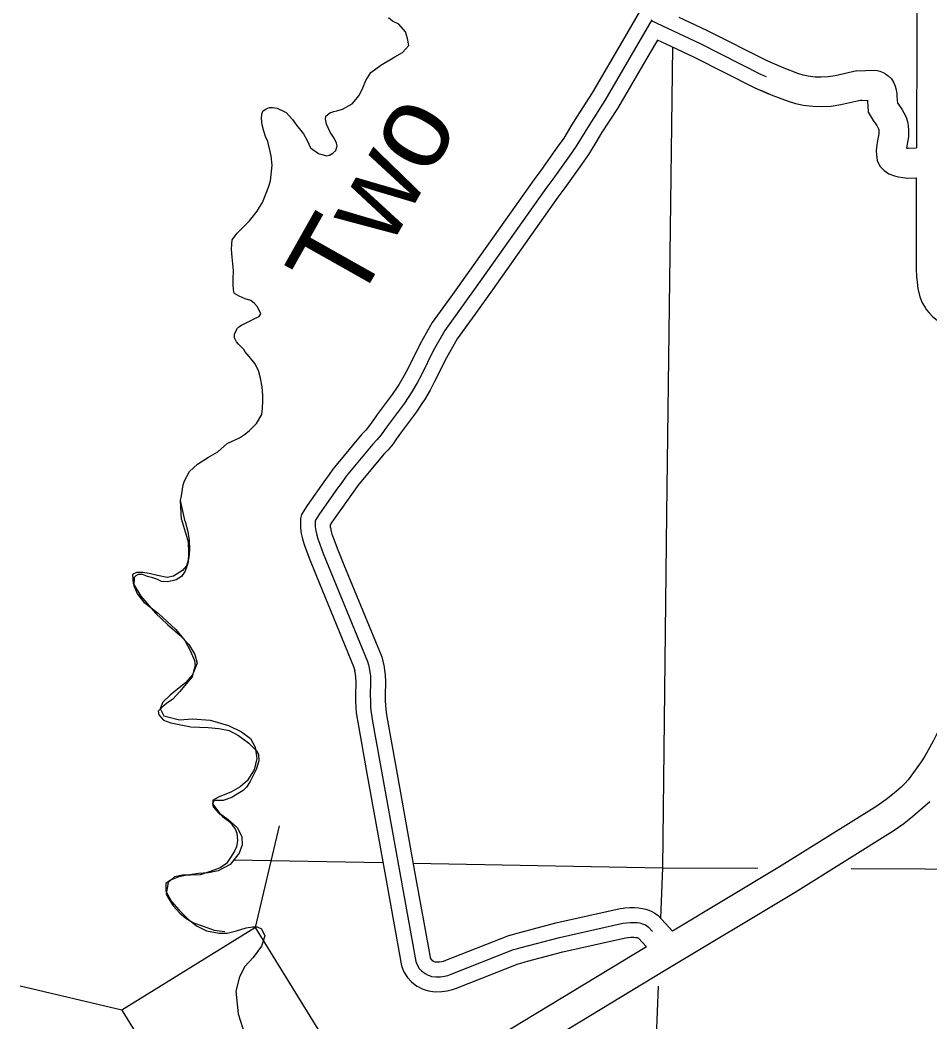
# Model space of a CAD drawing. Extents: x 1373094 to 1376427, y 1168361 to 1170494.
# Drawn here: x 1373276.1 to 1373352.6, y 1170074.3 to 1170158.6 of the extents above; entities that cross this region are included whole.
import ezdxf

# ---------------------------------------------------------------- set-up
doc = ezdxf.new("R2010")
doc.units = 0
doc.layers.add('R_Axis', color=7, linetype='Continuous')

msp = doc.modelspace()

# ---------------------------------------------------------------- linework, layer by layer
at = {"layer": 'R_Axis'}
for p, q in [((1373295.886, 1170082.215), (1373297.91, 1170090.779)), ((1373295.886, 1170082.215), (1373284.656, 1170075.278)), ((1373316.696, 1170048.524), (1373295.886, 1170082.215)), ((1373284.656, 1170075.278), (1373276.091, 1170077.302)), ((1373284.656, 1170075.278), (1373305.466, 1170041.587))]:
    msp.add_line(p, q, dxfattribs=at)
for points in [[(1373351.823, 1170177.904), (1373351.568, 1170164.434), (1373351.515, 1170157.726), (1373351.489, 1170147.798)], [(1373331.466, 1170164.647), (1373328.167, 1170159.211), (1373326.926, 1170157.083)], [(1373329.241, 1170158.572), (1373325.28, 1170151.78), (1373323.95, 1170149.722), (1373322.866, 1170147.935), (1373322.297, 1170147.141), (1373320.899, 1170145.182), (1373320.313, 1170144.388), (1373314.805, 1170136.587), (1373311.814, 1170132.432), (1373310.845, 1170130.73), (1373309.847, 1170128.71), (1373309.492, 1170128.037), (1373309.039, 1170127.278), (1373308.423, 1170126.334), (1373307.154, 1170124.661), (1373306.926, 1170124.323), (1373306.715, 1170124.019), (1373306.471, 1170123.681), (1373306.113, 1170123.242), (1373305.769, 1170122.885), (1373303.519, 1170120.178), (1373303.097, 1170119.587), (1373302.804, 1170119.182), (1373301.277, 1170117.021), (1373300.936, 1170116.481)], [(1373308.783, 1170156.41), (1373308.679, 1170157.011), (1373308.509, 1170157.577), (1373307.94, 1170158.208), (1373307.407, 1170158.472), (1373307.072, 1170158.737)], [(1373308.783, 1170156.41), (1373308.679, 1170157.011), (1373308.509, 1170157.577), (1373307.94, 1170158.208), (1373307.407, 1170158.472), (1373307.072, 1170158.737)], [(1373338.886, 1170153.774), (1373338.453, 1170153.956), (1373333.318, 1170156.548), (1373329.198, 1170158.501)], [(1373338.977, 1170155.091), (1373333.868, 1170157.671), (1373331.524, 1170158.782)], [(1373289.989, 1170116.379), (1373289.598, 1170118.148), (1373289.662, 1170118.549), (1373289.822, 1170119.452), (1373289.919, 1170119.786), (1373290.346, 1170120.589), (1373291.007, 1170121.194), (1373291.933, 1170121.8), (1373292.728, 1170122.239), (1373293.521, 1170122.944), (1373294.548, 1170123.417), (1373294.978, 1170123.687), (1373295.375, 1170123.99), (1373295.969, 1170124.627), (1373296.429, 1170125.364), (1373296.492, 1170125.865), (1373296.521, 1170126.566), (1373296.518, 1170126.967), (1373296.447, 1170127.701), (1373296.309, 1170128.434), (1373296.138, 1170129.068), (1373295.835, 1170129.667), (1373295.366, 1170130.265), (1373294.998, 1170130.663), (1373294.93, 1170130.83), (1373294.461, 1170131.294), (1373294.294, 1170131.493), (1373294.126, 1170131.826), (1373294.123, 1170132.16), (1373294.386, 1170132.629), (1373294.485, 1170132.763), (1373294.717, 1170132.898), (1373295.942, 1170133.506), (1373296.207, 1170133.607), (1373296.339, 1170133.842), (1373296.237, 1170134.108), (1373296.035, 1170134.474), (1373295.801, 1170134.706), (1373295.5, 1170134.972), (1373295.034, 1170135.102), (1373294.534, 1170135.333), (1373294.134, 1170135.565), (1373294.066, 1170135.664), (1373294.029, 1170136.232), (1373294.026, 1170136.766), (1373294.054, 1170137.5), (1373293.947, 1170138.601), (1373293.876, 1170139.268), (1373293.906, 1170139.702), (1373293.937, 1170140.069), (1373294.365, 1170140.639), (1373295.389, 1170141.68), (1373296.048, 1170142.485), (1373296.245, 1170142.82), (1373296.475, 1170143.222), (1373296.998, 1170144.493), (1373297.161, 1170145.028), (1373297.285, 1170146.364), (1373297.213, 1170147.131), (1373296.939, 1170148.331), (1373296.737, 1170148.764), (1373296.601, 1170149.197), (1373296.464, 1170149.73), (1373296.394, 1170150.264), (1373296.425, 1170150.631), (1373296.523, 1170150.899), (1373296.787, 1170151.101), (1373297.086, 1170151.202), (1373297.319, 1170151.204), (1373297.718, 1170151.139), (1373298.485, 1170150.777), (1373299.02, 1170150.179), (1373299.356, 1170149.714), (1373299.926, 1170148.983), (1373300.229, 1170148.417), (1373300.532, 1170147.818), (1373301.2, 1170147.321), (1373301.866, 1170147.125), (1373302.132, 1170147.193), (1373302.396, 1170147.361), (1373302.661, 1170147.597), (1373302.758, 1170147.964), (1373302.723, 1170148.198), (1373302.521, 1170148.631), (1373302.185, 1170149.129), (1373301.881, 1170149.795), (1373301.779, 1170150.228), (1373301.81, 1170150.462), (1373302.141, 1170150.764), (1373302.472, 1170150.867), (1373302.738, 1170150.935), (1373303.202, 1170151.071), (1373304.03, 1170151.51), (1373304.624, 1170152.214), (1373304.919, 1170152.85), (1373305.18, 1170153.486), (1373305.608, 1170154.156), (1373306.434, 1170154.761), (1373307.626, 1170155.469), (1373308.255, 1170155.84), (1373308.783, 1170156.41)], [(1373289.672, 1170116.536), (1373289.598, 1170118.148), (1373289.662, 1170118.549), (1373289.822, 1170119.452), (1373289.919, 1170119.786), (1373290.346, 1170120.589), (1373291.007, 1170121.194), (1373291.933, 1170121.8), (1373292.728, 1170122.239), (1373293.521, 1170122.944), (1373294.548, 1170123.417), (1373294.978, 1170123.687), (1373295.375, 1170123.99), (1373295.969, 1170124.627), (1373296.429, 1170125.364), (1373296.492, 1170125.865), (1373296.521, 1170126.566), (1373296.518, 1170126.967), (1373296.447, 1170127.701), (1373296.309, 1170128.434), (1373296.138, 1170129.068), (1373295.835, 1170129.667), (1373295.366, 1170130.265), (1373294.998, 1170130.663), (1373294.93, 1170130.83), (1373294.461, 1170131.294), (1373294.294, 1170131.493), (1373294.126, 1170131.826), (1373294.123, 1170132.16), (1373294.386, 1170132.629), (1373294.485, 1170132.763), (1373294.717, 1170132.898), (1373295.942, 1170133.506), (1373296.207, 1170133.607), (1373296.339, 1170133.842), (1373296.237, 1170134.108), (1373296.035, 1170134.474), (1373295.801, 1170134.706), (1373295.5, 1170134.972), (1373295.034, 1170135.102), (1373294.534, 1170135.333), (1373294.134, 1170135.565), (1373294.066, 1170135.664), (1373294.029, 1170136.232), (1373294.026, 1170136.766), (1373294.054, 1170137.5), (1373293.947, 1170138.601), (1373293.876, 1170139.268), (1373293.906, 1170139.702), (1373293.937, 1170140.069), (1373294.365, 1170140.639), (1373295.389, 1170141.68), (1373296.048, 1170142.485), (1373296.245, 1170142.82), (1373296.475, 1170143.222), (1373296.998, 1170144.493), (1373297.161, 1170145.028), (1373297.285, 1170146.364), (1373297.213, 1170147.131), (1373296.939, 1170148.331), (1373296.737, 1170148.764), (1373296.601, 1170149.197), (1373296.464, 1170149.73), (1373296.394, 1170150.264), (1373296.425, 1170150.631), (1373296.523, 1170150.899), (1373296.787, 1170151.101), (1373297.086, 1170151.202), (1373297.319, 1170151.204), (1373297.718, 1170151.139), (1373298.485, 1170150.777), (1373299.02, 1170150.179), (1373299.356, 1170149.714), (1373299.926, 1170148.983), (1373300.229, 1170148.417), (1373300.532, 1170147.818), (1373301.2, 1170147.321), (1373301.866, 1170147.125), (1373302.132, 1170147.193), (1373302.396, 1170147.361), (1373302.661, 1170147.597), (1373302.758, 1170147.964), (1373302.723, 1170148.198), (1373302.521, 1170148.631), (1373302.185, 1170149.129), (1373301.881, 1170149.795), (1373301.779, 1170150.228), (1373301.81, 1170150.462), (1373302.141, 1170150.764), (1373302.472, 1170150.867), (1373302.738, 1170150.935), (1373303.202, 1170151.071), (1373304.03, 1170151.51), (1373304.624, 1170152.214), (1373304.919, 1170152.85), (1373305.18, 1170153.486), (1373305.608, 1170154.156), (1373306.434, 1170154.761), (1373307.626, 1170155.469), (1373308.255, 1170155.84), (1373308.783, 1170156.41)], [(1373326.926, 1170157.083), (1373324.214, 1170152.434), (1373322.891, 1170150.385), (1373322.394, 1170149.567)], [(1373329.701, 1170156.879), (1373329.085, 1170155.823)], [(1373330.453, 1170156.522), (1373329.701, 1170156.879)], [(1373339.084, 1170152.335), (1373337.929, 1170152.82), (1373332.769, 1170155.425), (1373330.453, 1170156.522)], [(1373330.96, 1170156.282), (1373330.476, 1170117.025)], [(1373329.085, 1170155.823), (1373326.345, 1170151.125), (1373325.01, 1170149.058), (1373324.531, 1170148.27)], [(1373346.476, 1170154.276), (1373344.667, 1170153.877), (1373344.052, 1170153.785), (1373343.487, 1170153.75), (1373342.971, 1170153.767), (1373342.383, 1170153.844), (1373341.967, 1170153.934), (1373341.516, 1170154.064), (1373340.378, 1170154.504), (1373338.977, 1170155.091)], [(1373346.476, 1170154.276), (1373347.93, 1170154.338), (1373348.173, 1170154.303), (1373348.422, 1170154.255), (1373348.697, 1170154.137), (1373348.877, 1170154.037), (1373349.112, 1170153.876), (1373349.381, 1170153.607), (1373349.582, 1170153.276), (1373349.706, 1170152.987), (1373349.79, 1170152.692), (1373349.83, 1170152.362), (1373349.848, 1170152.139), (1373349.87, 1170151.848), (1373349.888, 1170151.568), (1373349.914, 1170151.528), (1373350.259, 1170151.07), (1373350.443, 1170150.745), (1373350.62, 1170150.376), (1373350.727, 1170150.029), (1373350.799, 1170149.681), (1373350.832, 1170149.265), (1373350.817, 1170148.745), (1373350.708, 1170148.104), (1373350.643, 1170147.786), (1373350.793, 1170147.774), (1373351.489, 1170147.798)], [(1373346.907, 1170151.811), (1373345.121, 1170151.417), (1373344.315, 1170151.297), (1373343.524, 1170151.247), (1373342.768, 1170151.273), (1373341.956, 1170151.378), (1373341.355, 1170151.509), (1373340.718, 1170151.693), (1373339.444, 1170152.184), (1373338.402, 1170152.621)], [(1373346.691, 1170151.782), (1373347.365, 1170151.811), (1373347.376, 1170151.671), (1373347.398, 1170151.332), (1373347.443, 1170150.8), (1373347.682, 1170150.376), (1373347.863, 1170150.096), (1373348.164, 1170149.696), (1373348.225, 1170149.589), (1373348.285, 1170149.462), (1373348.303, 1170149.404), (1373348.32, 1170149.326), (1373348.329, 1170149.202), (1373348.323, 1170148.992), (1373348.25, 1170148.562), (1373348.148, 1170148.061), (1373348.107, 1170147.597), (1373348.12, 1170147.214), (1373348.193, 1170146.736), (1373348.425, 1170146.26), (1373348.767, 1170145.896), (1373349.173, 1170145.614), (1373349.634, 1170145.443), (1373349.975, 1170145.356), (1373350.333, 1170145.302), (1373350.74, 1170145.271), (1373351.481, 1170145.296)], [(1373322.394, 1170149.567), (1373321.822, 1170148.624), (1373321.28, 1170147.868), (1373319.887, 1170145.916), (1373319.3, 1170145.119), (1373317.401, 1170142.43)], [(1373324.531, 1170148.27), (1373323.91, 1170147.245), (1373323.314, 1170146.414), (1373321.911, 1170144.448), (1373321.327, 1170143.656), (1373319.443, 1170140.988)], [(1373351.481, 1170145.296), (1373351.455, 1170137.596), (1373351.488, 1170136.994), (1373351.542, 1170136.51), (1373351.611, 1170135.971), (1373351.766, 1170135.282), (1373351.967, 1170134.769), (1373352.214, 1170134.388), (1373352.339, 1170134.194), (1373352.538, 1170133.952), (1373352.868, 1170133.586), (1373353.333, 1170133.225), (1373353.885, 1170132.91), (1373354.408, 1170132.719), (1373354.879, 1170132.61)], [(1373317.401, 1170142.43), (1373313.787, 1170137.312), (1373312.313, 1170135.264)], [(1373319.443, 1170140.988), (1373315.823, 1170135.861), (1373314.342, 1170133.803)], [(1373312.313, 1170135.264), (1373310.761, 1170133.108), (1373309.74, 1170131.317), (1373308.734, 1170129.279), (1373308.402, 1170128.649), (1373307.979, 1170127.941), (1373307.799, 1170127.665)], [(1373314.342, 1170133.803), (1373312.867, 1170131.755), (1373311.949, 1170130.143), (1373310.961, 1170128.142), (1373310.583, 1170127.425), (1373310.1, 1170126.616), (1373309.893, 1170126.299)], [(1373307.799, 1170127.665), (1373307.4, 1170127.054), (1373306.136, 1170125.388), (1373305.895, 1170125.029), (1373305.695, 1170124.742), (1373305.479, 1170124.443), (1373305.177, 1170124.072), (1373304.838, 1170123.72), (1373302.529, 1170120.942), (1373302.415, 1170120.783)], [(1373309.893, 1170126.299), (1373309.446, 1170125.613), (1373308.171, 1170123.933), (1373307.958, 1170123.617), (1373307.735, 1170123.297), (1373307.463, 1170122.92), (1373307.049, 1170122.411), (1373306.701, 1170122.051), (1373304.51, 1170119.414), (1373304.449, 1170119.329)], [(1373302.415, 1170120.783), (1373302.081, 1170120.317), (1373301.787, 1170119.909), (1373300.237, 1170117.715), (1373299.757, 1170116.954), (1373299.691, 1170116.628), (1373299.679, 1170116.512), (1373299.671, 1170116.416), (1373299.668, 1170116.298), (1373299.671, 1170116.069), (1373299.682, 1170115.842), (1373299.704, 1170115.602), (1373299.741, 1170115.365), (1373299.84, 1170114.922), (1373299.952, 1170114.528), (1373300.131, 1170114.039), (1373300.429, 1170113.223), (1373301.019, 1170111.787)], [(1373304.449, 1170119.329), (1373304.112, 1170118.858), (1373303.821, 1170118.455), (1373302.316, 1170116.326), (1373302.172, 1170116.097), (1373302.176, 1170116.016), (1373302.186, 1170115.915), (1373302.198, 1170115.833), (1373302.265, 1170115.535), (1373302.331, 1170115.3), (1373302.479, 1170114.898), (1373302.76, 1170114.128), (1373303.331, 1170112.737)], [(1373330.476, 1170117.025), (1373330.133, 1170087.243), (1373329.971, 1170083.005)], [(1373355.092, 1170117.343), (1373355.103, 1170110.899), (1373355.05, 1170104.967), (1373355.023, 1170104.393), (1373354.934, 1170103.73), (1373354.779, 1170103.035), (1373354.585, 1170102.338), (1373354.263, 1170101.289), (1373353.93, 1170100.257), (1373353.605, 1170099.412), (1373353.244, 1170098.575), (1373352.898, 1170097.89), (1373352.192, 1170096.646), (1373351.878, 1170096.173), (1373351.005, 1170094.956), (1373350.781, 1170094.657), (1373350.502, 1170094.331), (1373350.208, 1170094.031), (1373349.617, 1170093.52), (1373348.941, 1170092.999), (1373348.147, 1170092.442), (1373339.971, 1170087.341), (1373330.979, 1170081.927)], [(1373289.989, 1170116.379), (1373290.205, 1170115.532), (1373290.319, 1170114.767), (1373290.332, 1170114.033), (1373290.296, 1170113.315), (1373290.092, 1170112.66), (1373289.751, 1170112.254), (1373288.995, 1170111.772), (1373288.465, 1170111.679), (1373287.647, 1170111.831), (1373286.946, 1170112.001), (1373286.413, 1170112.075), (1373285.881, 1170112.081), (1373285.551, 1170111.925), (1373285.615, 1170111.159), (1373286.25, 1170110.086), (1373287.49, 1170108.657), (1373288.489, 1170107.708), (1373289.519, 1170106.826), (1373290.282, 1170106.04), (1373290.78, 1170105.198), (1373290.977, 1170104.451), (1373290.596, 1170103.476), (1373290.01, 1170102.798), (1373289.338, 1170102.285), (1373288.716, 1170101.772), (1373288.112, 1170101.177), (1373287.889, 1170100.656), (1373288.2, 1170100.044), (1373289.503, 1170099.701), (1373290.598, 1170099.772), (1373292.08, 1170099.666), (1373293.634, 1170099.228), (1373294.708, 1170098.697), (1373295.467, 1170098.111), (1373295.863, 1170097.384), (1373295.996, 1170096.452), (1373295.798, 1170095.497), (1373295.184, 1170094.551), (1373294.595, 1170094.057), (1373293.822, 1170093.608), (1373292.898, 1170093.257), (1373292.305, 1170092.929), (1373292.311, 1170092.612), (1373292.858, 1170091.838), (1373293.599, 1170091.302), (1373294.376, 1170090.615), (1373294.74, 1170089.838), (1373294.786, 1170089.171), (1373294.533, 1170088.466), (1373293.753, 1170087.517), (1373292.765, 1170086.981), (1373291.937, 1170086.832), (1373291.09, 1170086.767), (1373290.013, 1170086.613), (1373289.45, 1170086.486), (1373288.74, 1170086.205), (1373288.347, 1170085.931), (1373288.359, 1170085.281), (1373288.84, 1170084.422), (1373289.435, 1170083.716), (1373290.231, 1170082.913), (1373290.923, 1170082.358), (1373291.779, 1170081.957), (1373292.83, 1170081.743), (1373293.511, 1170081.739), (1373294.289, 1170081.937), (1373295.099, 1170082.203), (1373295.646, 1170082.28), (1373296.044, 1170082.287), (1373296.397, 1170082.127), (1373296.69, 1170081.532), (1373296.391, 1170080.642), (1373295.694, 1170079.711), (1373295.01, 1170078.931), (1373294.56, 1170078.088), (1373294.234, 1170076.864), (1373294.436, 1170074.966), (1373295.019, 1170073.124)], [(1373289.672, 1170116.536), (1373290.246, 1170114.67), (1373290.25, 1170113.702), (1373290.22, 1170112.967), (1373289.991, 1170112.198), (1373289.661, 1170111.762), (1373289.23, 1170111.46), (1373288.533, 1170111.289), (1373288.001, 1170111.32), (1373287.601, 1170111.518), (1373287.268, 1170111.65), (1373286.802, 1170111.747), (1373286.402, 1170111.912), (1373286.036, 1170111.91), (1373285.837, 1170111.809), (1373285.705, 1170111.675), (1373285.675, 1170110.974), (1373285.978, 1170110.274), (1373286.479, 1170109.609), (1373287.747, 1170108.648), (1373289.183, 1170107.287), (1373289.952, 1170106.356), (1373290.388, 1170105.524), (1373290.757, 1170104.691), (1373290.826, 1170104.258), (1373290.695, 1170103.756), (1373290.564, 1170103.322), (1373289.936, 1170102.55), (1373289.54, 1170102.081), (1373288.944, 1170101.444), (1373288.414, 1170101.074), (1373288.017, 1170100.738), (1373287.719, 1170100.436), (1373287.754, 1170100.102), (1373288.154, 1170099.67), (1373288.787, 1170099.44), (1373290.451, 1170099.115), (1373291.914, 1170099.056), (1373292.812, 1170098.96), (1373293.677, 1170098.798), (1373294.477, 1170098.368), (1373295.344, 1170097.738), (1373295.946, 1170097.107), (1373296.147, 1170096.775), (1373296.182, 1170096.241), (1373295.953, 1170095.505), (1373295.459, 1170094.501), (1373295.129, 1170094.032), (1373294.864, 1170093.763), (1373294.068, 1170093.259), (1373293.903, 1170093.158), (1373293.172, 1170092.92), (1373292.541, 1170092.917), (1373292.375, 1170092.849), (1373292.276, 1170092.648), (1373292.344, 1170092.382), (1373292.778, 1170091.883), (1373293.112, 1170091.551), (1373293.613, 1170091.186), (1373293.813, 1170091.021), (1373294.014, 1170090.721), (1373294.181, 1170090.522), (1373294.316, 1170090.155), (1373294.385, 1170089.555), (1373294.288, 1170089.02), (1373294.123, 1170088.652), (1373293.793, 1170088.116), (1373293.463, 1170087.614), (1373292.933, 1170087.244), (1373292.169, 1170086.973), (1373291.24, 1170086.667), (1373290.442, 1170086.63), (1373289.744, 1170086.626), (1373289.08, 1170086.489), (1373288.55, 1170086.019), (1373288.389, 1170085.05), (1373288.489, 1170084.817), (1373288.958, 1170084.052), (1373289.526, 1170083.42), (1373290.027, 1170083.022), (1373290.694, 1170082.625), (1373291.493, 1170082.329), (1373292.425, 1170082), (1373293.326, 1170081.895)], [(1373300.936, 1170116.481), (1373300.928, 1170116.442), (1373300.924, 1170116.399), (1373300.92, 1170116.349), (1373300.918, 1170116.289), (1373300.92, 1170116.105), (1373300.929, 1170115.929), (1373300.945, 1170115.758), (1373300.97, 1170115.599), (1373301.052, 1170115.229), (1373301.142, 1170114.914), (1373301.305, 1170114.468), (1373301.595, 1170113.676), (1373305.327, 1170104.589), (1373305.404, 1170104.318), (1373305.463, 1170104.066), (1373305.522, 1170103.713), (1373305.556, 1170103.385), (1373305.578, 1170102.877), (1373305.545, 1170101.741), (1373305.559, 1170101.291), (1373305.572, 1170100.823), (1373305.606, 1170100.461), (1373305.648, 1170100.134), (1373305.722, 1170099.726), (1373309.372, 1170079.356)], [(1373303.331, 1170112.737), (1373306.51, 1170105), (1373306.615, 1170104.632), (1373306.672, 1170104.385)], [(1373301.019, 1170111.787), (1373304.144, 1170104.179), (1373304.194, 1170104.004), (1373304.238, 1170103.817)], [(1373306.672, 1170104.385), (1373306.69, 1170104.311), (1373306.761, 1170103.88), (1373306.803, 1170103.477), (1373306.829, 1170102.887), (1373306.796, 1170101.742), (1373306.808, 1170101.327), (1373306.821, 1170100.898), (1373306.849, 1170100.599), (1373306.884, 1170100.325), (1373306.952, 1170099.949), (1373307.73, 1170095.61)], [(1373304.237, 1170103.821), (1373304.283, 1170103.546), (1373304.308, 1170103.294), (1373304.327, 1170102.868), (1373304.295, 1170101.74), (1373304.31, 1170101.254), (1373304.324, 1170100.747), (1373304.363, 1170100.324), (1373304.412, 1170099.942), (1373304.492, 1170099.504), (1373305.269, 1170095.169)], [(1373307.73, 1170095.61), (1373309.281, 1170086.948)], [(1373305.269, 1170095.169), (1373306.821, 1170086.507)], [(1373305.232, 1170063.404), (1373330.291, 1170078.595), (1373341.278, 1170085.21), (1373349.528, 1170090.357), (1373350.423, 1170090.984), (1373351.2, 1170091.584), (1373352.628, 1170092.819)], [(1373294.087, 1170087.924), (1373306.609, 1170087.687)], [(1373309.158, 1170087.639), (1373330.133, 1170087.243), (1373338.139, 1170087.211)], [(1373346.009, 1170087.179), (1373358.451, 1170087.129)], [(1373306.821, 1170086.507), (1373308.167, 1170078.991), (1373308.378, 1170078.507), (1373308.676, 1170078.027), (1373309.007, 1170077.666), (1373309.48, 1170077.289), (1373309.61, 1170077.224)], [(1373309.281, 1170086.948), (1373310.576, 1170079.721), (1373310.598, 1170079.671), (1373310.677, 1170079.544), (1373310.718, 1170079.499), (1373310.831, 1170079.409), (1373310.723, 1170079.463)], [(1373318.144, 1170081.815), (1373321.163, 1170082.611), (1373326.56, 1170083.81), (1373326.836, 1170083.853)], [(1373326.836, 1170083.853), (1373326.971, 1170083.874), (1373327.381, 1170083.903), (1373327.785, 1170083.903), (1373328.108, 1170083.887), (1373328.456, 1170083.837), (1373328.733, 1170083.767), (1373328.988, 1170083.675), (1373329.246, 1170083.564), (1373329.487, 1170083.426), (1373329.755, 1170083.236), (1373330.979, 1170081.927)], [(1373309.372, 1170079.356), (1373309.488, 1170079.089), (1373309.676, 1170078.785), (1373309.863, 1170078.582), (1373310.155, 1170078.349), (1373310.409, 1170078.223), (1373310.577, 1170078.161), (1373310.711, 1170078.115), (1373311.062, 1170078.076), (1373311.46, 1170078.087), (1373311.801, 1170078.131), (1373312.088, 1170078.197), (1373312.352, 1170078.299), (1373317.597, 1170080.361), (1373317.861, 1170080.436), (1373318.24, 1170080.547), (1373321.458, 1170081.396), (1373326.792, 1170082.581), (1373327.111, 1170082.631), (1373327.425, 1170082.653), (1373327.756, 1170082.653), (1373327.987, 1170082.642), (1373328.213, 1170082.609), (1373328.367, 1170082.57), (1373328.527, 1170082.512), (1373328.687, 1170082.444), (1373328.814, 1170082.37), (1373328.929, 1170082.289), (1373329.302, 1170081.89)], [(1373310.723, 1170079.463), (1373310.903, 1170079.373), (1373310.988, 1170079.342), (1373311.115, 1170079.328), (1373311.363, 1170079.334), (1373311.58, 1170079.362), (1373311.721, 1170079.395), (1373311.899, 1170079.464), (1373317.197, 1170081.547), (1373317.514, 1170081.637), (1373317.904, 1170081.751), (1373318.144, 1170081.815)], [(1373318.782, 1170079.398), (1373321.753, 1170080.181), (1373327.023, 1170081.352), (1373327.219, 1170081.383)], [(1373327.22, 1170081.383), (1373327.251, 1170081.388), (1373327.469, 1170081.403), (1373327.726, 1170081.403), (1373327.867, 1170081.396), (1373327.97, 1170081.381), (1373328.001, 1170081.373), (1373328.067, 1170081.349), (1373328.116, 1170081.328), (1373328.789, 1170080.608)], [(1373328.789, 1170080.608), (1373304.059, 1170065.614)], [(1373309.61, 1170077.224), (1373309.914, 1170077.073), (1373310.159, 1170076.983), (1373310.436, 1170076.889), (1373311.008, 1170076.824), (1373311.557, 1170076.839), (1373312.023, 1170076.899), (1373312.455, 1170076.999), (1373312.806, 1170077.134), (1373317.997, 1170079.175), (1373318.208, 1170079.235), (1373318.576, 1170079.343), (1373318.782, 1170079.398)], [(1373329.754, 1170077.295), (1373329.51, 1170070.896)]]:
    msp.add_lwpolyline(points, dxfattribs=at)

# ---------------------------------------------------------------- texts
msp.add_text('Two', height=7.04, rotation=60.60914, dxfattribs=at).set_placement((1373304.341, 1170134.306))

doc.saveas('drawing.dxf')
